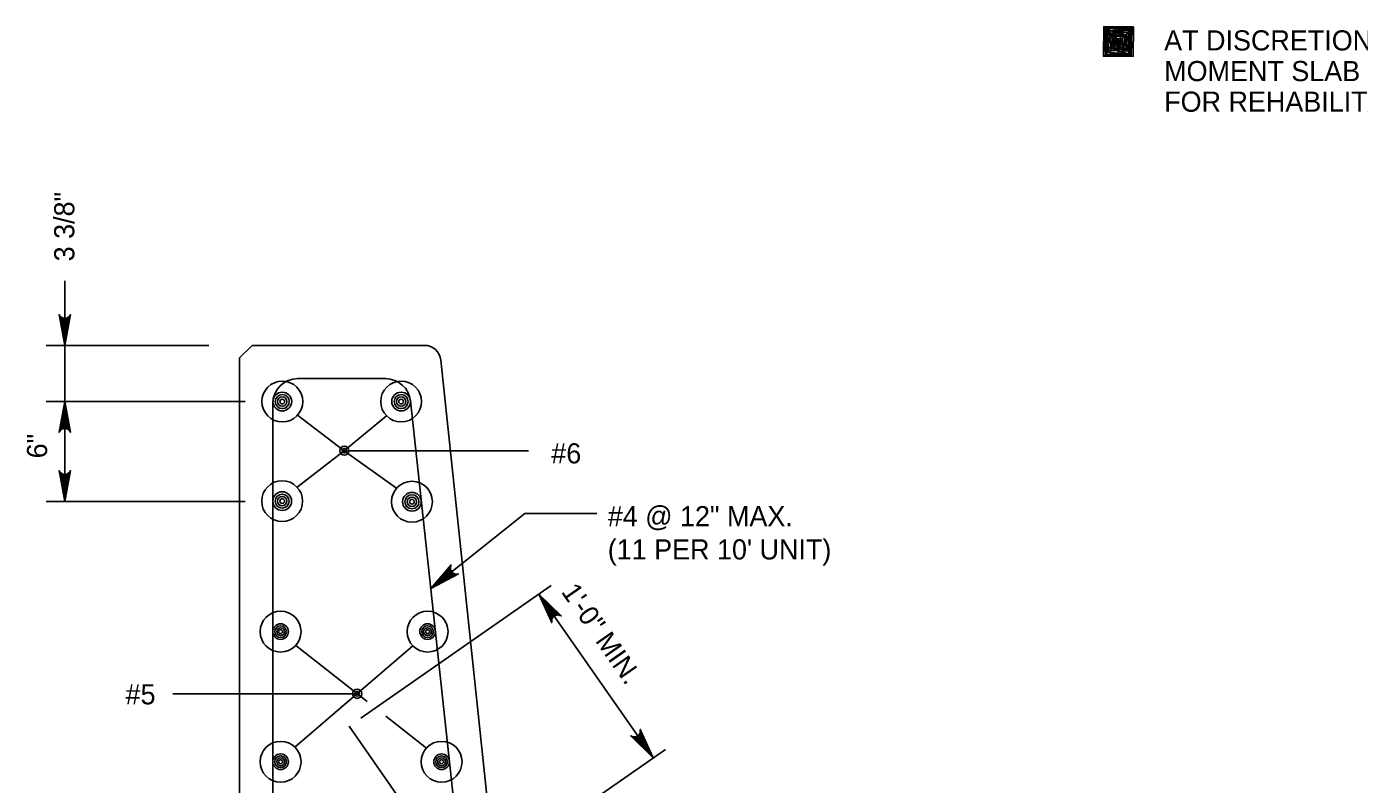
# Model space of a CAD drawing. Extents: x 638167 to 640248, y 296544 to 298920.
# Drawn here: x 638359.5 to 638562.8, y 297331.8 to 297447.4 of the extents above; entities that cross this region are included whole.
import ezdxf

# ---------------------------------------------------------------- set-up
doc = ezdxf.new("R2010")
doc.units = 0
for name, color, linetype in [('1', 7, 'Continuous'), ('50', 7, 'Continuous'), ('57', 7, 'Continuous')]:
    doc.layers.add(name, color=color, linetype=linetype)

# ---------------------------------------------------------------- blocks, each defined once
blk = doc.blocks.new('DIMDOT')
at = {"layer": '57'}
for radius in [2, 1]:
    blk.add_circle((0, 0), radius, dxfattribs=at)
blk = doc.blocks.new('BAR')
at = {"layer": '50'}
for radius in [2, 1.5, 1, 0.5]:
    blk.add_circle((0, 0), radius, dxfattribs=at)

msp = doc.modelspace()

# ---------------------------------------------------------------- linework, layer by layer
at = {"layer": '1'}
for p, q in [((638526.01, 297445.12), (638526.01, 297445.12)), ((638365.28, 297374.97), (638365.28, 297408.62)), ((638362.42, 297398.78), (638387.23, 297398.78)), ((638393.84, 297398.78), (638391.93, 297396.88)), ((638393.84, 297398.78), (638420.13, 297398.78)), ((638391.93, 297396.88), (638391.93, 297299.09)), ((638422.65, 297396.51), (638430.31, 297323.92)), ((638400.82, 297393.7), (638414.22, 297393.7)), ((638362.42, 297390.21), (638392.81, 297390.21)), ((638397.01, 297234.95), (638397.01, 297389.89)), ((638418.01, 297390.3), (638434.79, 297234.95)), ((638407.92, 297382.71), (638400.77, 297388.11)), ((638407.94, 297382.74), (638414.37, 297388.01)), ((638407.92, 297382.71), (638400.74, 297377.12)), ((638436.03, 297382.71), (638407.92, 297382.71)), ((638407.92, 297382.71), (638415.9, 297376.99)), ((638362.42, 297374.97), (638392.81, 297374.97)), ((638435.46, 297373.14), (638421.11, 297361.66)), ((638435.46, 297373.14), (638446.46, 297373.14)), ((638410.43, 297341.92), (638439.48, 297362.15)), ((638437.6, 297360.84), (638455.02, 297335.83)), ((638400.39, 297337.46), (638418.38, 297352.93)), ((638400.5, 297352.99), (638411.39, 297344.44)), ((638409.88, 297345.62), (638381.77, 297345.62)), ((638414.24, 297342.2), (638420.45, 297337.33)), ((638408.65, 297340.68), (638437.96, 297298.6)), ((638427.85, 297316.9), (638456.9, 297337.13))]:
    msp.add_line(p, q, dxfattribs=at)
for points in [[(638523.77, 297447.41), (638523.72, 297442.89), (638528.25, 297442.84), (638528.3, 297447.36), (638523.77, 297447.41), (638524.03, 297443.18), (638527.97, 297443.01), (638528.08, 297447.14), (638524.1, 297447.09), (638524.28, 297443.48), (638527.73, 297443.32), (638527.83, 297446.77), (638524.34, 297446.78), (638524.56, 297443.76), (638527.52, 297443.66), (638527.52, 297446.53), (638524.68, 297446.37), (638524.9, 297444.03), (638527.18, 297443.94), (638527.2, 297446.22), (638524.98, 297446.06), (638525.21, 297444.4), (638526.84, 297444.22), (638526.95, 297445.86), (638525.23, 297445.94), (638525.37, 297444.67), (638526.6, 297444.6), (638526.61, 297445.46), (638525.75, 297445.65), (638525.68, 297444.91), (638526.3, 297444.85), (638526.36, 297445.22), (638526.05, 297445.22), (638523.98, 297447.28), (638528.17, 297447.17), (638523.87, 297442.96), (638527.91, 297443.2), (638524.04, 297447.09), (638527.82, 297445.72), (638524.15, 297446.41), (638527.71, 297444.4), (638524.11, 297445.33), (638527.61, 297443.75), (638524.29, 297444.34), (638527.36, 297443.32), (638524.74, 297443.32), (638525.52, 297447.01), (638526.03, 297443.37), (638526.5, 297446.94), (638527.7, 297443.23), (638528.01, 297446.95), (638526.66, 297443.92), (638523.92, 297447.15), (638524.21, 297443.24), (638524.83, 297446.4), (638527.77, 297446.9), (638524.47, 297447.15)], [(638365.28, 297398.78), (638364.4, 297403.48), (638364.53, 297403.3), (638364.65, 297403.12), (638364.81, 297403.03), (638364.97, 297402.93), (638365.13, 297402.91), (638365.28, 297402.88), (638365.44, 297402.91), (638365.6, 297402.93), (638365.76, 297403.03), (638365.91, 297403.12), (638366.04, 297403.3), (638366.16, 297403.48), (638365.28, 297398.78), (638366.04, 297403.3), (638365.91, 297403.12), (638365.28, 297398.78), (638365.76, 297403.03), (638365.6, 297402.93), (638365.28, 297398.78), (638365.44, 297402.91), (638365.28, 297402.88), (638365.28, 297398.78), (638365.13, 297402.91), (638364.97, 297402.93), (638365.28, 297398.78), (638364.81, 297403.03), (638364.65, 297403.12), (638365.28, 297398.78), (638364.53, 297403.3)], [(638365.28, 297390.21), (638366.16, 297385.51), (638366.04, 297385.69), (638365.91, 297385.87), (638365.76, 297385.97), (638365.6, 297386.06), (638365.44, 297386.09), (638365.28, 297386.12), (638365.13, 297386.09), (638364.97, 297386.06), (638364.81, 297385.97), (638364.65, 297385.87), (638364.53, 297385.69), (638364.4, 297385.51), (638365.28, 297390.21), (638364.53, 297385.69), (638364.65, 297385.87), (638365.28, 297390.21), (638364.81, 297385.97), (638364.97, 297386.06), (638365.28, 297390.21), (638365.13, 297386.09), (638365.28, 297386.12), (638365.28, 297390.21), (638365.44, 297386.09), (638365.6, 297386.06), (638365.28, 297390.21), (638365.76, 297385.97), (638365.91, 297385.87), (638365.28, 297390.21), (638366.04, 297385.69)], [(638365.28, 297374.97), (638364.4, 297379.67), (638364.53, 297379.49), (638364.65, 297379.31), (638364.81, 297379.21), (638364.97, 297379.12), (638365.13, 297379.09), (638365.28, 297379.07), (638365.44, 297379.09), (638365.6, 297379.12), (638365.76, 297379.21), (638365.91, 297379.31), (638366.04, 297379.49), (638366.16, 297379.67), (638365.28, 297374.97), (638366.04, 297379.49), (638365.91, 297379.31), (638365.28, 297374.97), (638365.76, 297379.21), (638365.6, 297379.12), (638365.28, 297374.97), (638365.44, 297379.09), (638365.28, 297379.07), (638365.28, 297374.97), (638365.13, 297379.09), (638364.97, 297379.12), (638365.28, 297374.97), (638364.81, 297379.21), (638364.65, 297379.31), (638365.28, 297374.97), (638364.53, 297379.49)], [(638421.11, 297361.66), (638424.22, 297365.28), (638424.16, 297365.07), (638424.1, 297364.86), (638424.12, 297364.68), (638424.15, 297364.5), (638424.23, 297364.36), (638424.3, 297364.22), (638424.42, 297364.11), (638424.54, 297364.01), (638424.71, 297363.94), (638424.88, 297363.88), (638425.1, 297363.89), (638425.32, 297363.91), (638421.11, 297361.66), (638425.1, 297363.89), (638424.88, 297363.88), (638421.11, 297361.66), (638424.71, 297363.94), (638424.54, 297364.01), (638421.11, 297361.66), (638424.42, 297364.11), (638424.3, 297364.22), (638421.11, 297361.66), (638424.23, 297364.36), (638424.15, 297364.5), (638421.11, 297361.66), (638424.12, 297364.68), (638424.1, 297364.86), (638421.11, 297361.66), (638424.16, 297365.07)], [(638437.6, 297360.84), (638441.01, 297357.49), (638440.8, 297357.57), (638440.6, 297357.64), (638440.41, 297357.63), (638440.23, 297357.62), (638440.09, 297357.55), (638439.94, 297357.48), (638439.83, 297357.37), (638439.71, 297357.26), (638439.64, 297357.09), (638439.56, 297356.92), (638439.56, 297356.7), (638439.56, 297356.48), (638437.6, 297360.84), (638439.56, 297356.7), (638439.56, 297356.92), (638437.6, 297360.84), (638439.64, 297357.09), (638439.71, 297357.26), (638437.6, 297360.84), (638439.83, 297357.37), (638439.94, 297357.48), (638437.6, 297360.84), (638440.09, 297357.55), (638440.23, 297357.62), (638437.6, 297360.84), (638440.41, 297357.63), (638440.6, 297357.64), (638437.6, 297360.84), (638440.8, 297357.57)], [(638455.02, 297335.83), (638451.61, 297339.18), (638451.82, 297339.1), (638452.03, 297339.03), (638452.21, 297339.04), (638452.39, 297339.05), (638452.54, 297339.12), (638452.68, 297339.19), (638452.79, 297339.3), (638452.91, 297339.41), (638452.98, 297339.58), (638453.06, 297339.75), (638453.06, 297339.97), (638453.06, 297340.19), (638455.02, 297335.83), (638453.06, 297339.97), (638453.06, 297339.75), (638455.02, 297335.83), (638452.98, 297339.58), (638452.91, 297339.41), (638455.02, 297335.83), (638452.79, 297339.3), (638452.68, 297339.19), (638455.02, 297335.83), (638452.54, 297339.12), (638452.39, 297339.05), (638455.02, 297335.83), (638452.21, 297339.04), (638452.03, 297339.03), (638455.02, 297335.83), (638451.82, 297339.1)]]:
    msp.add_lwpolyline(points, dxfattribs=at)
for centre in [(638398.46, 297390.21), (638416.59, 297390.21), (638398.44, 297375.01), (638418.24, 297374.92), (638398.2, 297355.1), (638420.62, 297355.1), (638398.2, 297335.24), (638422.76, 297335.24)]:
    msp.add_circle(centre, 3.12, dxfattribs=at)
for centre, radius, start, end in [((638420.13, 297396.24), 2.54, 6.0207, 90), ((638400.82, 297389.89), 3.81, 90, 180), ((638414.22, 297389.89), 3.81, 6.1633, 90)]:
    msp.add_arc(centre, radius, start, end, dxfattribs=at)

# ---------------------------------------------------------------- block references
at = {"layer": '1', "rotation": -90.00000000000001}
for p, xscale, yscale in [((638398.46, 297390.21), 0.714376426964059, 0.714376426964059), ((638416.59, 297390.21), 0.714376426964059, 0.714376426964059), ((638398.44, 297375.01), 0.714376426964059, 0.714376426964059), ((638418.24, 297374.92), 0.714376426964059, 0.714376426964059), ((638398.2, 297355.1), 0.5953136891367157, 0.5953136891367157), ((638420.62, 297355.1), 0.5953136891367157, 0.5953136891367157), ((638398.2, 297335.24), 0.5953136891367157, 0.5953136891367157), ((638422.76, 297335.24), 0.5953136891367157, 0.5953136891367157)]:
    msp.add_blockref('BAR', p, dxfattribs=dict(at, xscale=xscale, yscale=yscale))
at = {"layer": '1', "xscale": 0.349999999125, "yscale": 0.349999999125}
for p in [(638407.92, 297382.71), (638409.88, 297345.62)]:
    msp.add_blockref('DIMDOT', p, dxfattribs=at)

# ---------------------------------------------------------------- texts
at = {"layer": '1'}
for s, p in [('AT DISCRETION OF DISTRICT BRIDGE ENGINEER, ', (638533, 297443.78)), ('MOMENT SLAB WIDTH MAY BE REDUCED TO 4\'-0". ', (638533, 297439.1)), ('FOR REHABILITATION PROJECTS, SEE SHEET 7', (638533, 297434.43)), ('#6', (638439.5, 297380.77)), ('#4 @ 12" MAX.', (638448.11, 297371.18)), ("(11 PER 10' UNIT)", (638448.11, 297366.11)), ('#5', (638374.55, 297344))]:
    msp.add_text(s, height=3.072, dxfattribs=at).set_placement(p)
for s, height, rotation, p in [('3 3/8"', 3.072, 90, (638366.73, 297411.6)), ('6"', 3.072, 90, (638362.58, 297381.54)), ('1\'-0" MIN.', 3, 304.8545, (638440.91, 297361.17))]:
    msp.add_text(s, height=height, rotation=rotation, dxfattribs=at).set_placement(p)

doc.saveas('drawing.dxf')
